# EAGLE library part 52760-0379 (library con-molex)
MOLEX Connector SD-52760-**79 Source: 52760-1079_sd molex.pdf
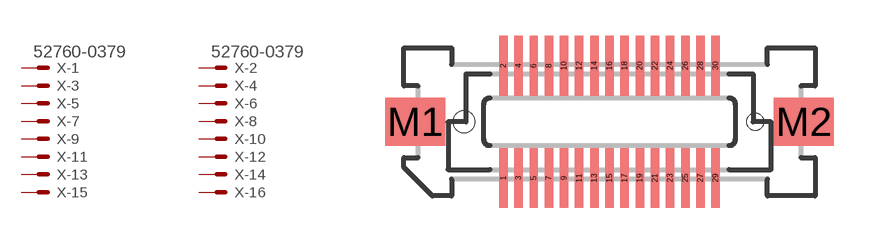
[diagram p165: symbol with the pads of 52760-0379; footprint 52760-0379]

Designator prefix X; gates -1=MV -2=MV -3=M -4=M -5=M -6=M -7=M -8=M -9=M -10=M -11=M -12=M -13=M -14=M -15=M -16=M -17=M -18=M -19=M -20=M -21=M -22=M -23=M -24=M -25=M -26=M -27=M -28=M -29=M -30=M

## 52760-0379 (MPN: 52760-0379; OC_FARNELL: unknown; OC_NEWARK: 92M6431)  [52760-0379]
1  -1:S  pas
2  -2:S  pas
3  -3:S  pas
4  -4:S  pas
5  -5:S  pas
6  -6:S  pas
7  -7:S  pas
8  -8:S  pas
9  -9:S  pas
10  -10:S  pas
11  -11:S  pas
12  -12:S  pas
13  -13:S  pas
14  -14:S  pas
15  -15:S  pas
16  -16:S  pas
17  -17:S  pas
18  -18:S  pas
19  -19:S  pas
20  -20:S  pas
21  -21:S  pas
22  -22:S  pas
23  -23:S  pas
24  -24:S  pas
25  -25:S  pas
26  -26:S  pas
27  -27:S  pas
28  -28:S  pas
29  -29:S  pas
30  -30:S  pas

## Footprint 52760-0379 (pad centres in mm)
MOLEX Connector SD-52760-**79 Source: 52760-1079_sd molex.pdf
smd 0.35 x 2.5: 1 -4.445,-2.35; 2 -4.445,2.35; 3 -3.81,-2.35; 4 -3.81,2.35; 5 -3.175,-2.35; 6 -3.175,2.35; 7 -2.54,-2.35; 8 -2.54,2.35; 9 -1.905,-2.35; 10 -1.905,2.35; 11 -1.27,-2.35; 12 -1.27,2.35; 13 -0.635,-2.35; 14 -0.635,2.35; 15 0,-2.35; 16 0,2.35; 17 0.635,-2.35; 18 0.635,2.35; 19 1.27,-2.35; 20 1.27,2.35; 21 1.905,-2.35; 22 1.905,2.35; 23 2.54,-2.35; 24 2.54,2.35; 25 3.175,-2.35; 26 3.175,2.35; 27 3.81,-2.35; 28 3.81,2.35; 29 4.445,-2.35; 30 4.445,2.35
smd 2.5 x 2: M1 -8.137,0; M2 8.137,0
hole 0.9 at -6.098,0
hole 0.7 at 6.098,0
